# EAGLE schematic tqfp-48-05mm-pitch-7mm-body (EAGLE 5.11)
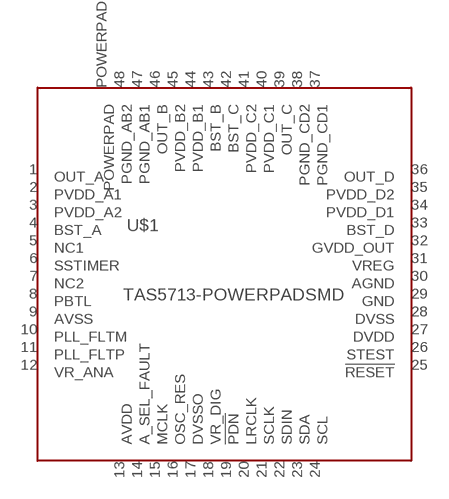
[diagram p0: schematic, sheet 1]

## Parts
U$1  TAS5713-POWERPADSMD  [TQFP-48-POWERPAD]
Unconnected: U$1.1(OUT_A) U$1.2(PVDD_A1) U$1.3(PVDD_A2) U$1.4(BST_A) U$1.5(NC1) U$1.6(SSTIMER) U$1.7(NC2) U$1.8(PBTL) U$1.9(AVSS) U$1.10(PLL_FLTM) U$1.11(PLL_FLTP) U$1.12(VR_ANA) U$1.13(AVDD) U$1.14(A_SEL_FAULT) U$1.15(MCLK) U$1.16(OSC_RES) U$1.17(DVSSO) U$1.18(VR_DIG) U$1.19(!PDN) U$1.20(LRCLK) U$1.21(SCLK) U$1.22(SDIN) U$1.23(SDA) U$1.24(SCL) U$1.25(!RESET) U$1.26(STEST) U$1.27(DVDD) U$1.28(DVSS) U$1.29(GND) U$1.30(AGND) U$1.31(VREG) U$1.32(GVDD_OUT) U$1.33(BST_D) U$1.34(PVDD_D1) U$1.35(PVDD_D2) U$1.36(OUT_D) U$1.37(PGND_CD1) U$1.38(PGND_CD2) U$1.39(OUT_C) U$1.40(PVDD_C1) U$1.41(PVDD_C2) U$1.42(BST_C) U$1.43(BST_B) U$1.44(PVDD_B1) U$1.45(PVDD_B2) U$1.46(OUT_B) U$1.47(PGND_AB1) U$1.48(PGND_AB2) U$1.POWERPAD

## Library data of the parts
U$1 = trl:TAS5713-POWERPAD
